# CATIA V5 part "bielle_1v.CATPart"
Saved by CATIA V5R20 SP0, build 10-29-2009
Part number: bielle_1v
Bounding box of the stored display mesh (mm): x 63.532 to 130.639, y 75.389 to 127.267, z 96.842 to 136.842
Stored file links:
  D:\ecole\thinkmotion\IAO\bielle_1v.CATPart
  D:\ecole\thinkmotion\IAO\mecanisme coulisseau.CATProduct
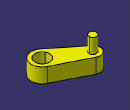
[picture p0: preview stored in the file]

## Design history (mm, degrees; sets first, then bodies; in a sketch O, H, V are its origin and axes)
External parameters (linked from other documents)
  External.rayon_pivot_bati = 10 mm
Set1
  Plane1: linked copy from another document
  Point1 to Point4: linked copy from another document
  Plane2: linked copy from another document
  Point5: linked copy from another document
  Plane3: linked copy from another document
Body1 (main body)
  Sketch1 on Plane1, origin (0, 0, 116.8423), H (1, 0, 0), V (0, -1, 0)
    arc A1 centre (73.5019, -117.2959) radius 10 from (78.015, -126.2196) to (67.3033, -109.4488) cw
    point P1 (73.5019, -117.2959)
    point P2 (78.015, -126.2196)
    point P3 (67.3033, -109.4488)
    reference projected point E1 (73.5019, -117.2959) from Point1
    reference projected point E2 (65.0742, -122.6787) from Point2
    arc A2 centre (115.6401, -90.3817) radius 15 from (122.4097, -103.7672) to (106.3421, -78.6111) ccw
    point P4 (115.6401, -90.3817)
    point P5 (122.4097, -103.7672)
    point P6 (106.3421, -78.6111)
    reference projected point E3 (115.6401, -90.3817) from Point3
    reference projected point E4 (128.2815, -82.3075) from Point4
    line L1 (122.4097, -103.7672) -> (78.015, -126.2196)
    point P7 (122.4097, -103.7672)
    point P8 (78.015, -126.2196)
    line L2 (106.3421, -78.6111) -> (67.3033, -109.4488)
    point P9 (106.3421, -78.6111)
    point P10 (67.3033, -109.4488)
    coincidence: P1 E1, A1 E2, P4 E3, A2 E4, P7 P5, P8 P2, P10 P3, P9 P6
    tangency: L2 A1, L2 A2, L1 A2, L1 A1
  Pad1: profile Sketch1, direction (0, 0, -1), up to Plane2
  Sketch2 on Plane1, origin (0, 0, 116.8423), H (1, 0, 0), V (0, -1, 0)
    circle A1 centre (73.5019, -117.2959) radius 5
    point P1 (73.5019, -117.2959)
    reference projected point E1 (73.5019, -117.2959) from Point1
    reference projected point E2 (69.2881, -119.9873) from Point5
    coincidence: P1 E1, A1 E2
  Pad2: profile Sketch2, direction (0, 0, -1), up to Plane3
  Sketch3 on Plane1, origin (0, 0, 116.8423), H (1, 0, 0), V (0, -1, 0)
    point P1 (115.6401, -90.3817)
    reference projected point E1 (115.6401, -90.3817) from Point3
    coincidence: E1 P1
  Hole1: placed by Sketch3, at (115.6401, 90.3817, 116.8423) direction (0, 0, 1), diameter 20 {= External.rayon_pivot_bati *2}, up to Plane2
